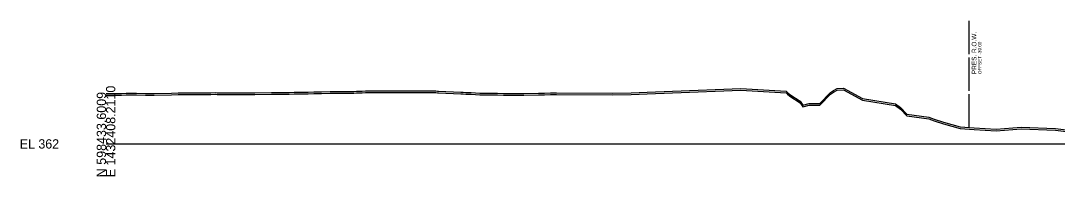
# Model space of a CAD drawing. Extents: x -26 to 2203, y -10 to 12201.
# Drawn here: x -25.7 to 286.5, y 5490.3 to 5537 of the extents above; entities that cross this region are included whole.
import ezdxf

# ---------------------------------------------------------------- set-up
doc = ezdxf.new("R2010")
doc.units = 0
for name, color, linetype in [('DESIGN - SHEET - Light Grid', 7, 'Continuous'), ('SURVEY - GROUND - Bottom of Topsoil Layer', 7, 'Continuous'), ('SURVEY - GROUND - Top of Ground', 7, 'Continuous'), ('SURVEY - PROPERTY - ROW Lines', 7, 'Continuous'), ('SURVEY - PROPERTY - ROW Lines Text', 7, 'Continuous')]:
    doc.layers.add(name, color=color, linetype=linetype)

msp = doc.modelspace()

# ---------------------------------------------------------------- linework, layer by layer
at = {"layer": 'DESIGN - SHEET - Light Grid'}
msp.add_line((0, 5500), (300, 5500), dxfattribs=at)
at = {"layer": 'SURVEY - GROUND - Bottom of Topsoil Layer'}
for p, q in [((0, 5514.59), (1.24, 5514.6)), ((1.24, 5514.6), (3.73, 5514.66)), ((3.73, 5514.66), (4.63, 5514.67)), ((4.63, 5514.67), (6.04, 5514.69)), ((6.04, 5514.69), (6.54, 5514.7)), ((6.54, 5514.7), (7.57, 5514.69)), ((7.57, 5514.69), (9.19, 5514.7)), ((9.19, 5514.7), (11.84, 5514.65)), ((11.84, 5514.65), (12.16, 5514.65)), ((12.16, 5514.65), (14.49, 5514.66)), ((14.49, 5514.66), (19.69, 5514.77)), ((19.69, 5514.77), (21.73, 5514.79)), ((21.73, 5514.79), (22.03, 5514.79)), ((22.03, 5514.79), (22.44, 5514.79)), ((22.44, 5514.79), (23.03, 5514.79)), ((23.03, 5514.79), (27.74, 5514.81)), ((27.74, 5514.81), (29.57, 5514.83)), ((29.57, 5514.83), (30.4, 5514.84)), ((30.4, 5514.84), (31.53, 5514.87)), ((31.53, 5514.87), (33.05, 5514.89)), ((33.05, 5514.89), (33.49, 5514.88)), ((33.49, 5514.88), (34.74, 5514.86)), ((34.74, 5514.86), (35.7, 5514.84)), ((35.7, 5514.84), (36.77, 5514.84)), ((36.77, 5514.84), (43.65, 5514.83)), ((43.65, 5514.83), (44.82, 5514.86)), ((44.82, 5514.86), (49.79, 5514.91)), ((49.79, 5514.91), (53.09, 5514.95)), ((53.09, 5514.95), (53.58, 5514.96)), ((53.58, 5514.96), (54.25, 5514.96)), ((54.25, 5514.96), (55.2, 5514.97)), ((55.2, 5514.97), (56.67, 5515.01)), ((56.67, 5515.01), (60.93, 5515.06)), ((60.93, 5515.06), (62.6, 5515.12)), ((62.6, 5515.12), (64.86, 5515.1)), ((64.86, 5515.1), (67.5, 5515.19)), ((67.5, 5515.19), (68.95, 5515.2)), ((68.95, 5515.2), (70.16, 5515.21)), ((70.16, 5515.21), (72.37, 5515.21)), ((72.37, 5515.21), (72.81, 5515.21)), ((72.81, 5515.21), (74.65, 5515.27)), ((74.65, 5515.27), (75.46, 5515.29)), ((75.46, 5515.29), (77.13, 5515.36)), ((77.13, 5515.36), (78.11, 5515.4)), ((78.11, 5515.4), (79.9, 5515.44)), ((79.9, 5515.44), (80.76, 5515.46)), ((80.76, 5515.46), (81.22, 5515.45)), ((81.22, 5515.45), (83.41, 5515.44)), ((83.41, 5515.44), (84.45, 5515.43)), ((84.45, 5515.43), (86.06, 5515.4)), ((86.06, 5515.4), (86.42, 5515.4)), ((86.42, 5515.4), (87.43, 5515.4)), ((87.43, 5515.4), (88.38, 5515.4)), ((88.38, 5515.4), (88.71, 5515.41)), ((88.71, 5515.41), (89.41, 5515.41)), ((89.41, 5515.41), (91.77, 5515.41)), ((91.77, 5515.41), (93.5, 5515.4)), ((93.5, 5515.4), (94.15, 5515.41)), ((94.15, 5515.41), (94.95, 5515.41)), ((94.95, 5515.41), (96.22, 5515.41)), ((96.22, 5515.41), (96.66, 5515.4)), ((96.66, 5515.4), (97.59, 5515.4)), ((97.59, 5515.4), (99.31, 5515.4)), ((99.31, 5515.4), (99.79, 5515.37)), ((99.79, 5515.37), (100.14, 5515.35)), ((100.14, 5515.35), (106.9, 5515.08)), ((106.9, 5515.08), (107.55, 5515.05)), ((107.55, 5515.05), (108.4, 5514.98)), ((108.4, 5514.98), (110.01, 5514.9)), ((110.01, 5514.9), (112.57, 5514.76)), ((112.57, 5514.76), (113.96, 5514.76)), ((113.96, 5514.76), (115.22, 5514.75)), ((115.22, 5514.75), (115.82, 5514.74)), ((115.82, 5514.74), (117.87, 5514.72)), ((117.87, 5514.72), (119.74, 5514.66)), ((119.74, 5514.66), (120.52, 5514.65)), ((120.52, 5514.65), (121.7, 5514.63)), ((121.7, 5514.63), (123.17, 5514.62)), ((123.17, 5514.62), (123.66, 5514.61)), ((123.66, 5514.61), (125.06, 5514.61)), ((125.06, 5514.61), (125.82, 5514.61)), ((125.82, 5514.61), (130.28, 5514.76)), ((130.28, 5514.76), (132.03, 5514.77)), ((132.03, 5514.77), (133.84, 5514.81)), ((133.84, 5514.81), (135.72, 5514.84)), ((135.72, 5514.84), (152.42, 5514.75)), ((152.42, 5514.75), (158.19, 5514.83)), ((158.19, 5514.83), (163.02, 5515.03)), ((163.02, 5515.03), (170.6, 5515.36)), ((170.6, 5515.36), (191.17, 5516.15)), ((191.17, 5516.15), (204.81, 5515.3)), ((204.81, 5515.3), (205.24, 5514.98)), ((205.24, 5514.98), (205.98, 5514.35)), ((205.98, 5514.35), (209.08, 5512.36)), ((215.04, 5511.66), (218.24, 5514.97)), ((218.24, 5514.97), (219.07, 5515.55)), ((219.07, 5515.55), (220.18, 5516.17)), ((220.18, 5516.17), (222.11, 5516.27)), ((222.11, 5516.27), (227.84, 5513.17)), ((209.08, 5512.36), (209.88, 5511.15)), ((209.88, 5511.15), (211.78, 5511.62)), ((211.78, 5511.62), (215.04, 5511.66)), ((227.84, 5513.17), (237.81, 5511.51)), ((237.81, 5511.51), (239.25, 5510.39)), ((239.25, 5510.39), (241.24, 5508.44)), ((241.24, 5508.44), (247.87, 5507.53)), ((247.87, 5507.53), (249.4, 5506.93)), ((249.4, 5506.93), (252.25, 5506.04)), ((252.25, 5506.04), (257.21, 5504.65)), ((257.21, 5504.65), (261.46, 5504.36)), ((261.46, 5504.36), (268.14, 5503.93)), ((268.14, 5503.93), (275.58, 5504.51)), ((275.58, 5504.51), (286.01, 5504.12)), ((286.01, 5504.12), (293.25, 5503.26))]:
    msp.add_line(p, q, dxfattribs=at)
at = {"layer": 'SURVEY - GROUND - Top of Ground'}
for p, q in [((170.6, 5515.86), (191.17, 5516.65)), ((191.17, 5516.65), (204.81, 5515.8)), ((219.07, 5516.05), (220.18, 5516.67)), ((220.18, 5516.67), (222.11, 5516.77)), ((222.11, 5516.77), (227.84, 5513.67)), ((0, 5515.09), (1.24, 5515.1)), ((1.24, 5515.1), (3.73, 5515.16)), ((3.73, 5515.16), (4.63, 5515.17)), ((4.63, 5515.17), (6.04, 5515.19)), ((6.04, 5515.19), (6.54, 5515.2)), ((6.54, 5515.2), (7.57, 5515.19)), ((7.57, 5515.19), (9.19, 5515.2)), ((9.19, 5515.2), (11.84, 5515.15)), ((11.84, 5515.15), (12.16, 5515.15)), ((12.16, 5515.15), (14.49, 5515.16)), ((14.49, 5515.16), (19.69, 5515.27)), ((19.69, 5515.27), (21.73, 5515.29)), ((21.73, 5515.29), (22.03, 5515.29)), ((22.03, 5515.29), (22.44, 5515.29)), ((22.44, 5515.29), (23.03, 5515.29)), ((23.03, 5515.29), (27.74, 5515.31)), ((27.74, 5515.31), (29.57, 5515.33)), ((29.57, 5515.33), (30.4, 5515.34)), ((30.4, 5515.34), (31.53, 5515.37)), ((31.53, 5515.37), (33.05, 5515.39)), ((33.05, 5515.39), (33.49, 5515.38)), ((33.49, 5515.38), (34.74, 5515.36)), ((34.74, 5515.36), (35.7, 5515.34)), ((35.7, 5515.34), (36.77, 5515.34)), ((36.77, 5515.34), (43.65, 5515.33)), ((43.65, 5515.33), (44.82, 5515.36)), ((44.82, 5515.36), (49.79, 5515.41)), ((49.79, 5515.41), (53.09, 5515.45)), ((53.09, 5515.45), (53.58, 5515.46)), ((53.58, 5515.46), (54.25, 5515.46)), ((54.25, 5515.46), (55.2, 5515.47)), ((55.2, 5515.47), (56.67, 5515.51)), ((56.67, 5515.51), (60.93, 5515.56)), ((60.93, 5515.56), (62.6, 5515.62)), ((62.6, 5515.62), (64.86, 5515.6)), ((64.86, 5515.6), (67.5, 5515.69)), ((67.5, 5515.69), (68.95, 5515.7)), ((68.95, 5515.7), (70.16, 5515.71)), ((70.16, 5515.71), (72.37, 5515.71)), ((72.37, 5515.71), (72.81, 5515.71)), ((72.81, 5515.71), (74.65, 5515.77)), ((74.65, 5515.77), (75.46, 5515.79)), ((75.46, 5515.79), (77.13, 5515.86)), ((77.13, 5515.86), (78.11, 5515.9)), ((78.11, 5515.9), (79.9, 5515.94)), ((79.9, 5515.94), (80.76, 5515.96)), ((80.76, 5515.96), (81.22, 5515.95)), ((81.22, 5515.95), (83.41, 5515.94)), ((83.41, 5515.94), (84.45, 5515.93)), ((84.45, 5515.93), (86.06, 5515.9)), ((86.06, 5515.9), (86.42, 5515.9)), ((86.42, 5515.9), (87.43, 5515.9)), ((87.43, 5515.9), (88.38, 5515.9)), ((88.38, 5515.9), (88.71, 5515.91)), ((88.71, 5515.91), (89.41, 5515.91)), ((89.41, 5515.91), (91.77, 5515.91)), ((91.77, 5515.91), (93.5, 5515.9)), ((93.5, 5515.9), (94.15, 5515.91)), ((94.15, 5515.91), (94.95, 5515.91)), ((94.95, 5515.91), (96.22, 5515.91)), ((96.22, 5515.91), (96.66, 5515.9)), ((96.66, 5515.9), (97.59, 5515.9)), ((97.59, 5515.9), (99.31, 5515.9)), ((99.31, 5515.9), (99.79, 5515.87)), ((99.79, 5515.87), (100.14, 5515.85)), ((100.14, 5515.85), (106.9, 5515.58)), ((106.9, 5515.58), (107.55, 5515.55)), ((107.55, 5515.55), (108.4, 5515.48)), ((108.4, 5515.48), (110.01, 5515.4)), ((110.01, 5515.4), (112.57, 5515.26)), ((112.57, 5515.26), (113.96, 5515.26)), ((113.96, 5515.26), (115.22, 5515.25)), ((115.22, 5515.25), (115.82, 5515.24)), ((115.82, 5515.24), (117.87, 5515.22)), ((117.87, 5515.22), (119.74, 5515.16)), ((119.74, 5515.16), (120.52, 5515.15)), ((120.52, 5515.15), (121.7, 5515.13)), ((121.7, 5515.13), (123.17, 5515.12)), ((123.17, 5515.12), (123.66, 5515.11)), ((123.66, 5515.11), (125.06, 5515.11)), ((125.06, 5515.11), (125.82, 5515.11)), ((125.82, 5515.11), (130.28, 5515.26)), ((130.28, 5515.26), (132.03, 5515.27)), ((132.03, 5515.27), (133.84, 5515.31)), ((133.84, 5515.31), (135.72, 5515.34)), ((135.72, 5515.34), (152.42, 5515.25)), ((152.42, 5515.25), (158.19, 5515.33)), ((158.19, 5515.33), (163.02, 5515.53)), ((163.02, 5515.53), (170.6, 5515.86)), ((204.81, 5515.8), (205.24, 5515.48)), ((205.24, 5515.48), (205.98, 5514.85)), ((205.98, 5514.85), (209.08, 5512.86)), ((215.04, 5512.16), (218.24, 5515.47)), ((218.24, 5515.47), (219.07, 5516.05)), ((227.84, 5513.67), (237.81, 5512.01)), ((209.08, 5512.86), (209.88, 5511.65)), ((209.88, 5511.65), (211.78, 5512.12)), ((211.78, 5512.12), (215.04, 5512.16)), ((237.81, 5512.01), (239.25, 5510.89)), ((239.25, 5510.89), (241.24, 5508.94)), ((241.24, 5508.94), (247.87, 5508.03)), ((247.87, 5508.03), (249.4, 5507.43)), ((249.4, 5507.43), (252.25, 5506.54)), ((252.25, 5506.54), (257.21, 5505.15)), ((257.21, 5505.15), (261.46, 5504.86)), ((261.46, 5504.86), (268.14, 5504.43)), ((268.14, 5504.43), (275.58, 5505.01)), ((275.58, 5505.01), (286.01, 5504.62)), ((286.01, 5504.62), (293.25, 5503.76))]:
    msp.add_line(p, q, dxfattribs=at)
at = {"layer": 'SURVEY - PROPERTY - ROW Lines'}
for p, q in [((260, 5526.96), (260, 5536.96)), ((260, 5515.96), (260, 5525.96)), ((260, 5504.96), (260, 5514.96))]:
    msp.add_line(p, q, dxfattribs=at)

# ---------------------------------------------------------------- texts
at = {"layer": 'DESIGN - SHEET - Light Grid'}
for s, p in [('E 1432408.2110', (2.8, 5490)), ('N 598433.6009', (0, 5490))]:
    msp.add_text(s, height=2.8, rotation=90, dxfattribs=at).set_placement(p)
msp.add_text('EL 362', height=2.8, dxfattribs=at).set_placement((-26, 5498.6))
at = {"layer": 'SURVEY - PROPERTY - ROW Lines Text'}
for s, height, p in [('PRES. R.O.W.', 1.4, (262.15, 5520.96)), ('OFFSET -39.00', 1, (263.65, 5520.96))]:
    msp.add_text(s, height=height, rotation=90, dxfattribs=at).set_placement(p)

doc.saveas('drawing.dxf')
